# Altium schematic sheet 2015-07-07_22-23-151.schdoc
size 231 x 111 mm; SheetNumber: 1; SheetTotal: 1
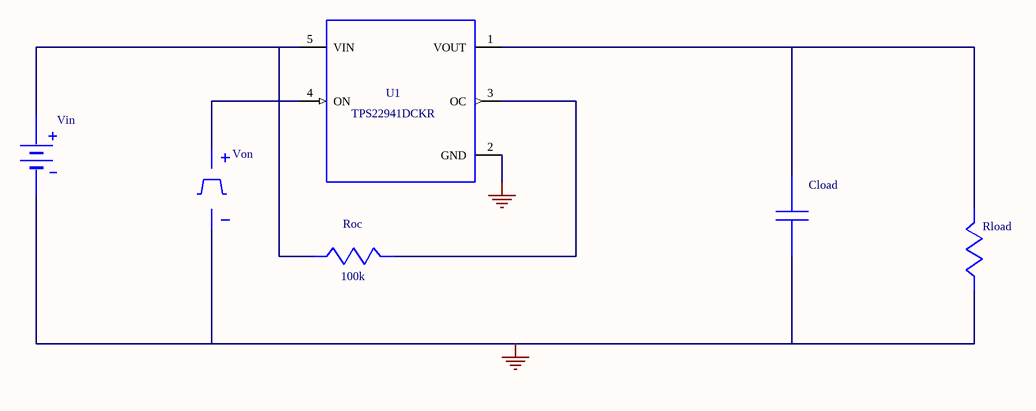
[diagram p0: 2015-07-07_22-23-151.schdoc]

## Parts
Cload  GRM21BR71E104KA01L  (value not drawn)
Rload  WB_LOAD_RESISTOR  (value not drawn)
Roc  value 100k  (hidden comment: CRCW0402100KFKED)
U1  TPS22941DCKR
Vin  WB_BATTERY  (value not drawn)
Von  WB_PRIM_PWL_VOLTAGE_SOURCE  (value not drawn)

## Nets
0: Cload.2 Rload.2 U1.2(GND) Vin.2(-) Von.2(-)
NetCload_1: Cload.1 Rload.1 U1.1(VOUT)
NetRoc_1: Roc.1 U1.3(OC)
NetRoc_2: Roc.2 U1.5(VIN) Vin.1(+)
NetU1_4: U1.4(ON) Von.1(+)

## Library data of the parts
Cload = GRM21BR71E104KA01L: WB_PRIMITIVE_CAP; Manufacturer Name: WB_PRIMITIVE_CAPACITOR; Value: UNLISTED
Rload = WB_LOAD_RESISTOR: Value: UNLISTED
Roc = CRCW0402100KFKED: Manufacturer Name: Vishay-Dale
U1 = TPS22941DCKR: Manufacturer Name: Texas Instruments; Value: UNLISTED
Vin = WB_BATTERY: Value: UNLISTED
Von = WB_PRIM_PWL_VOLTAGE_SOURCE: WB_PRIM_PWL_VOLT; Value: UNLISTED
